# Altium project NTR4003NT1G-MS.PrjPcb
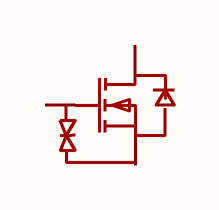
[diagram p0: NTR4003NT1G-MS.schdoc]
1 sheet, 1 parts. Net scope: global (net labels, ports and power ports of the same name join across sheets).

## Sheet NTR4003NT1G-MS.schdoc
size 127 x 101 mm

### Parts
Q?  ntr4003nt1g-ms  [SOT-23-3_L2.9-W1.3-P1.90-LS2.4-BR]  (value not drawn)

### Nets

Not connected (* = marked no-connect by the designer): Q? 1(G) 2(S) 3(D)

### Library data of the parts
Q? = ntr4003nt1g-ms: 数量:1个N沟道;漏源电压(Vdss):30V;连续漏极电流(Id):500mA;导通电阻(RDS(on)):1Ω@10V;耗散功率(Pd):350mW;阈值电压(Vgs(th)):1.1V;; Manufacturer: MSKSEMI(美森科); AddInBom: yes; ModelId: c62791f0466c4ae2a892c056b845b0ca; ModelName: SOT-23-3P_L2.9-W1.3-H1.0-LS2.4-P0.95; ModelTransform: 98.425,114.173,0,180,0,0,0.0005,-0.0005,0; Number: 1个N沟道; Drain to Source Voltage: 30V; Current - Continuous Drain(Id): 500mA; RDS(on): 1Ω@10V; Pd - Power Dissipation: 350mW; Gate Threshold Voltage (Vgs(th)): 1.1V; Gate Charge(Qg): 3.7nC@10V; Input Capacitance(Ciss): 25.5pF; Reverse Transfer Capacitance (Crss@Vds): 7.8pF; Type: N沟道; Output Capacitance(Coss): 17pF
